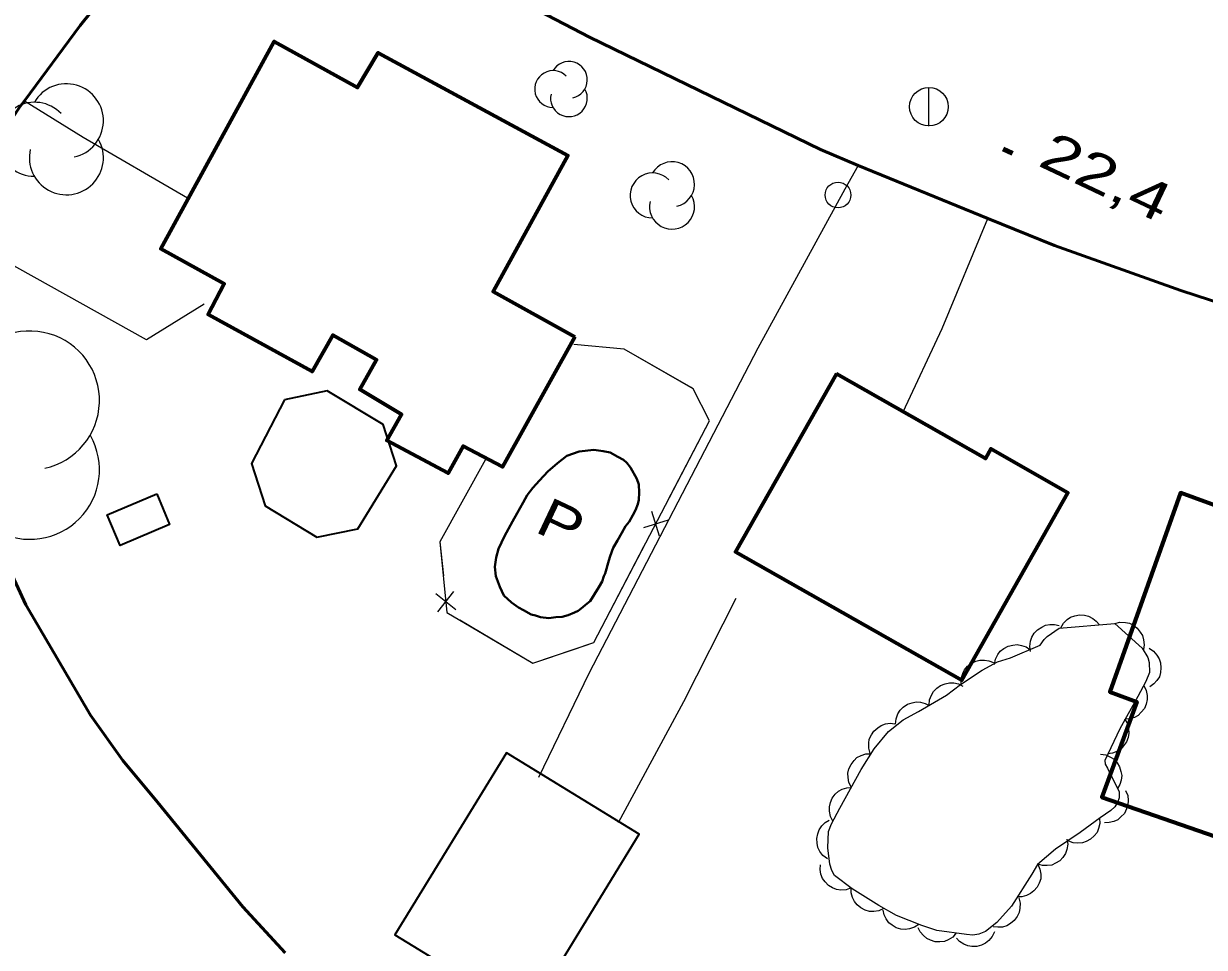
# Model space of a CAD drawing. Extents: x 356765 to 358572, y 5103174 to 5104650.
# Drawn here: x 357286.24 to 357332.12, y 5103742.66 to 5103778.57 of the extents above; entities that cross this region are included whole.
import ezdxf

# ---------------------------------------------------------------- set-up
doc = ezdxf.new("R2010")
doc.units = 0
doc.header["$LTSCALE"] = 0.6
doc.linetypes.add('DOT_DASHED', pattern=[7.7, 5, -1.2, 0.3, -1.2])
for name, color, linetype, lineweight in [('19', 7, 'Continuous', 13), ('21', 7, 'Continuous', 53), ('3', 7, 'Continuous', 140), ('31', 7, 'Continuous', 70), ('36', 7, 'Continuous', 13), ('37', 7, 'Continuous', 13), ('38', 7, 'Continuous', 40), ('44', 7, 'Continuous', 25)]:
    doc.layers.add(name, color=color, linetype=linetype, lineweight=lineweight)

msp = doc.modelspace()

# ---------------------------------------------------------------- linework, layer by layer
at = {"layer": '19'}
for points in [[(357286.27, 5103775.57), (357288.55, 5103774.15), (357292.61, 5103771.8)], [(357318.67, 5103773.06), (357318.15, 5103772.14), (357314.77, 5103765.95), (357308.2, 5103753.31), (357306.24, 5103749.26)], [(357320.42, 5103763.48), (357321.93, 5103766.72), (357323.7, 5103771)], [(357293.25, 5103767.66), (357291.02, 5103766.28), (357283.5, 5103770.46)], [(357309.36, 5103747.52), (357311.89, 5103752.22), (357313.93, 5103756.23)]]:
    msp.add_lwpolyline(points, dxfattribs=at)
at = {"layer": '21'}
for points in [[(357280.14, 5103794.63), (357289.29, 5103788.13), (357299.84, 5103782.26), (357304.62, 5103779.93), (357308.23, 5103778.04), (357317.21, 5103773.67), (357318.67, 5103773.06), (357323.7, 5103771), (357326.29, 5103769.94), (357331.21, 5103768.2), (357336.81, 5103766.37)], [(357283.01, 5103768.41), (357283.3, 5103769.8), (357283.5, 5103770.46), (357283.66, 5103770.96), (357284.91, 5103773.56), (357286.09, 5103775.33), (357286.27, 5103775.57), (357288.44, 5103778.49), (357289.72, 5103780.1), (357290.52, 5103781.01), (357292.93, 5103783.3), (357295.18, 5103784.86)], [(357296.4, 5103742.45), (357294.76, 5103744.23), (357291.44, 5103748.3), (357290.1, 5103749.92), (357288.84, 5103751.69), (357286.33, 5103755.98), (357285.04, 5103758.74)]]:
    msp.add_lwpolyline(points, dxfattribs=at)
at = {"layer": '3'}
msp.add_line((357324.3, 5103773.7), (357324.66, 5103773.53), dxfattribs=at)
at = {"layer": '31'}
for points in [[(357307.66, 5103766.4), (357304.85, 5103761.34), (357303.32, 5103762.15), (357302.73, 5103761.09), (357300.35, 5103762.37), (357300.92, 5103763.38), (357299.31, 5103764.34), (357299.95, 5103765.5), (357298.25, 5103766.46), (357297.45, 5103765.04), (357293.41, 5103767.26), (357294.03, 5103768.46), (357291.57, 5103769.82), (357295.97, 5103777.88), (357299.21, 5103776.09), (357300.01, 5103777.44), (357307.39, 5103773.44), (357304.49, 5103768.16), (357307.66, 5103766.4)], [(357317.82, 5103764.96), (357313.9, 5103758.04), (357322.69, 5103753.05), (357326.82, 5103760.33), (357323.82, 5103762.04), (357323.61, 5103761.67), (357317.82, 5103764.96)], [(357337.58, 5103759.41), (357334.61, 5103760.46), (357334.13, 5103759.26), (357331.19, 5103760.33), (357328.45, 5103752.59), (357329.49, 5103752.21), (357328.14, 5103748.5), (357334.28, 5103746.38), (357334.62, 5103747.4), (357335.54, 5103747.09), (357339.2, 5103757.37), (357337.12, 5103758.16), (357337.58, 5103759.41)]]:
    msp.add_lwpolyline(points, close=True, dxfattribs=at)
at = {"layer": '31', "lineweight": 35}
for points in [[(357296.38, 5103763.95), (357295.09, 5103761.47), (357295.63, 5103759.82), (357297.63, 5103758.61), (357299.22, 5103758.93), (357300.73, 5103761.38), (357300.21, 5103762.98), (357298.03, 5103764.29), (357296.38, 5103763.95)], [(357291.41, 5103760.29), (357291.91, 5103759.1), (357289.99, 5103758.28), (357289.49, 5103759.47), (357291.41, 5103760.29)], [(357305.83, 5103739.98), (357310.16, 5103747.06), (357305, 5103750.22), (357300.67, 5103743.15), (357305.83, 5103739.98)]]:
    msp.add_lwpolyline(points, close=True, dxfattribs=at)
at = {"layer": '36'}
msp.add_line((357321.41, 5103774.58), (357321.41, 5103776.08), dxfattribs=at)
for centre, radius in [((357321.4159, 5103775.3398), 0.75), ((357317.8838, 5103771.9071), 0.5)]:
    msp.add_circle(centre, radius, dxfattribs=at)
at = {"layer": '37'}
for p, q in [((357310.95, 5103758.65), (357310.65, 5103759.6)), ((357311.28, 5103759.27), (357310.32, 5103758.97)), ((357302.26, 5103756.42), (357303.03, 5103755.79)), ((357302.33, 5103755.71), (357302.96, 5103756.49))]:
    msp.add_line(p, q, dxfattribs=at)
for points in [[(357304.19, 5103761.63), (357302.41, 5103758.42), (357302.69, 5103755.68), (357306.03, 5103753.71), (357308.39, 5103754.51), (357312.89, 5103763.13), (357312.26, 5103764.37), (357309.58, 5103765.92), (357307.62, 5103766.09)], [(357312.18, 5103764.42), (357309.58, 5103765.92), (357307.62, 5103766.09)], [(357311.26, 5103760.01), (357312.89, 5103763.13), (357312.26, 5103764.37), (357312.18, 5103764.42)], [(357304.19, 5103761.63), (357302.41, 5103758.42), (357302.55, 5103757.1)], [(357307.64, 5103754.25), (357308.39, 5103754.51), (357310.34, 5103758.24)], [(357303.19, 5103755.39), (357306.03, 5103753.71), (357307.64, 5103754.25)]]:
    msp.add_lwpolyline(points, dxfattribs=at)
at = {"layer": '38'}
msp.add_lwpolyline([(357308.98, 5103757.7), (357309.03, 5103757.87), (357309.15, 5103758.19), (357309.32, 5103758.48), (357309.48, 5103758.78), (357309.63, 5103759.04), (357309.77, 5103759.2), (357309.91, 5103759.46), (357310.02, 5103759.65), (357310.1, 5103759.89), (357310.15, 5103760.06), (357310.16, 5103760.34), (357310.14, 5103760.65), (357310.07, 5103760.88), (357309.82, 5103761.31), (357309.68, 5103761.49), (357309.55, 5103761.61), (357309.33, 5103761.73), (357309.03, 5103761.9), (357308.76, 5103761.95), (357308.4, 5103762), (357307.83, 5103761.94), (357307.35, 5103761.77), (357306.99, 5103761.48), (357306.61, 5103761.16), (357306.28, 5103760.81), (357306.02, 5103760.52), (357305.81, 5103760.24), (357305.65, 5103759.95), (357305.42, 5103759.54), (357305.23, 5103759.21), (357304.92, 5103758.65), (357304.69, 5103758.15), (357304.6, 5103757.81), (357304.55, 5103757.45), (357304.59, 5103757.09), (357304.74, 5103756.67), (357304.9, 5103756.34), (357305.2, 5103756.07), (357305.47, 5103755.87), (357305.66, 5103755.77), (357305.96, 5103755.6), (357306.13, 5103755.56), (357306.33, 5103755.49), (357306.65, 5103755.46), (357306.92, 5103755.5), (357307.17, 5103755.51), (357307.4, 5103755.57), (357307.65, 5103755.68), (357307.79, 5103755.74), (357307.97, 5103755.89), (357308.07, 5103755.98), (357308.25, 5103756.12), (357308.59, 5103756.66), (357308.72, 5103756.88), (357308.78, 5103757.09), (357308.84, 5103757.2), (357308.98, 5103757.7)], close=True, dxfattribs=at)
at = {"layer": '44'}
for points in [[(357326.54, 5103755.08), (357326.64, 5103755.26), (357326.79, 5103755.4), (357326.92, 5103755.5), (357327.09, 5103755.55), (357327.27, 5103755.59), (357327.46, 5103755.57), (357327.62, 5103755.54), (357327.78, 5103755.45), (357327.92, 5103755.34), (357328.04, 5103755.2)], [(357325.37, 5103754.16), (357325.34, 5103754.36), (357325.37, 5103754.56), (357325.42, 5103754.72), (357325.51, 5103754.87), (357325.64, 5103755.01), (357325.8, 5103755.11), (357325.94, 5103755.18), (357326.12, 5103755.21), (357326.3, 5103755.21), (357326.48, 5103755.17)], [(357328.64, 5103755.25), (357328.84, 5103755.3), (357329.05, 5103755.29), (357329.21, 5103755.26), (357329.36, 5103755.18), (357329.51, 5103755.07), (357329.63, 5103754.91), (357329.72, 5103754.78), (357329.76, 5103754.61), (357329.78, 5103754.42), (357329.75, 5103754.24)], [(357323.96, 5103753.66), (357324, 5103753.86), (357324.09, 5103754.04), (357324.19, 5103754.18), (357324.33, 5103754.28), (357324.49, 5103754.37), (357324.68, 5103754.41), (357324.84, 5103754.43), (357325.01, 5103754.4), (357325.19, 5103754.34), (357325.34, 5103754.24)], [(357329.97, 5103754.29), (357330.14, 5103754.18), (357330.27, 5103754.02), (357330.36, 5103753.88), (357330.41, 5103753.72), (357330.43, 5103753.53), (357330.41, 5103753.34), (357330.37, 5103753.18), (357330.27, 5103753.04), (357330.15, 5103752.9), (357330, 5103752.79)], [(357322.67, 5103752.9), (357322.67, 5103753.11), (357322.73, 5103753.3), (357322.8, 5103753.45), (357322.92, 5103753.59), (357323.07, 5103753.7), (357323.24, 5103753.78), (357323.4, 5103753.83), (357323.57, 5103753.83), (357323.75, 5103753.8), (357323.92, 5103753.73)], [(357321.43, 5103752.07), (357321.44, 5103752.28), (357321.52, 5103752.47), (357321.59, 5103752.61), (357321.72, 5103752.74), (357321.87, 5103752.84), (357322.05, 5103752.91), (357322.21, 5103752.95), (357322.38, 5103752.94), (357322.56, 5103752.9), (357322.73, 5103752.82)], [(357329.77, 5103752.84), (357329.86, 5103752.65), (357329.9, 5103752.45), (357329.9, 5103752.29), (357329.86, 5103752.12), (357329.79, 5103751.95), (357329.67, 5103751.8), (357329.55, 5103751.68), (357329.4, 5103751.6), (357329.22, 5103751.54), (357329.04, 5103751.53)], [(357320.12, 5103751.34), (357320.14, 5103751.55), (357320.21, 5103751.74), (357320.3, 5103751.88), (357320.42, 5103752), (357320.58, 5103752.11), (357320.76, 5103752.17), (357320.92, 5103752.2), (357321.09, 5103752.19), (357321.27, 5103752.14), (357321.43, 5103752.06)], [(357319.14, 5103750.2), (357319.08, 5103750.4), (357319.08, 5103750.6), (357319.1, 5103750.76), (357319.18, 5103750.92), (357319.28, 5103751.07), (357319.43, 5103751.2), (357319.56, 5103751.29), (357319.73, 5103751.35), (357319.91, 5103751.37), (357320.09, 5103751.35)], [(357329.02, 5103751.54), (357329.13, 5103751.36), (357329.17, 5103751.16), (357329.19, 5103750.99), (357329.16, 5103750.82), (357329.09, 5103750.65), (357328.98, 5103750.49), (357328.87, 5103750.37), (357328.72, 5103750.28), (357328.55, 5103750.21), (357328.37, 5103750.18)], [(357318.41, 5103748.88), (357318.31, 5103749.07), (357318.28, 5103749.27), (357318.27, 5103749.43), (357318.31, 5103749.6), (357318.39, 5103749.77), (357318.51, 5103749.92), (357318.62, 5103750.04), (357318.78, 5103750.12), (357318.96, 5103750.18), (357319.14, 5103750.19)], [(357328.08, 5103750.17), (357328.29, 5103750.14), (357328.47, 5103750.06), (357328.61, 5103749.97), (357328.73, 5103749.84), (357328.82, 5103749.68), (357328.88, 5103749.5), (357328.91, 5103749.34), (357328.89, 5103749.16), (357328.84, 5103748.99), (357328.75, 5103748.83)], [(357317.68, 5103747.57), (357317.59, 5103747.75), (357317.55, 5103747.96), (357317.55, 5103748.12), (357317.59, 5103748.29), (357317.66, 5103748.46), (357317.78, 5103748.61), (357317.9, 5103748.73), (357318.05, 5103748.81), (357318.23, 5103748.86), (357318.41, 5103748.88)], [(357329.06, 5103748.76), (357329.14, 5103748.57), (357329.16, 5103748.37), (357329.15, 5103748.2), (357329.1, 5103748.04), (357329.01, 5103747.87), (357328.88, 5103747.73), (357328.76, 5103747.62), (357328.6, 5103747.55), (357328.42, 5103747.51), (357328.24, 5103747.5)], [(357328.05, 5103747.68), (357328.06, 5103747.48), (357328.01, 5103747.28), (357327.95, 5103747.13), (357327.84, 5103746.99), (357327.7, 5103746.87), (357327.53, 5103746.78), (357327.38, 5103746.72), (357327.2, 5103746.71), (357327.02, 5103746.73), (357326.85, 5103746.79)], [(357317.47, 5103746.1), (357317.3, 5103746.23), (357317.18, 5103746.39), (357317.1, 5103746.54), (357317.07, 5103746.71), (357317.06, 5103746.89), (357317.1, 5103747.08), (357317.15, 5103747.23), (357317.25, 5103747.38), (357317.39, 5103747.51), (357317.54, 5103747.6)], [(357326.78, 5103746.87), (357326.81, 5103746.67), (357326.77, 5103746.47), (357326.72, 5103746.31), (357326.62, 5103746.16), (357326.5, 5103746.03), (357326.33, 5103745.93), (357326.19, 5103745.86), (357326.01, 5103745.84), (357325.83, 5103745.84), (357325.65, 5103745.89)], [(357318.39, 5103744.97), (357318.2, 5103744.9), (357317.99, 5103744.89), (357317.83, 5103744.91), (357317.67, 5103744.97), (357317.51, 5103745.07), (357317.38, 5103745.21), (357317.28, 5103745.34), (357317.22, 5103745.51), (357317.19, 5103745.69), (357317.2, 5103745.87)], [(357325.65, 5103745.89), (357325.73, 5103745.7), (357325.76, 5103745.5), (357325.76, 5103745.33), (357325.7, 5103745.16), (357325.62, 5103745), (357325.49, 5103744.86), (357325.37, 5103744.75), (357325.21, 5103744.68), (357325.03, 5103744.63), (357324.85, 5103744.62)], [(357319.66, 5103744.17), (357319.47, 5103744.08), (357319.27, 5103744.06), (357319.11, 5103744.06), (357318.94, 5103744.11), (357318.77, 5103744.2), (357318.63, 5103744.32), (357318.52, 5103744.44), (357318.45, 5103744.6), (357318.4, 5103744.78), (357318.39, 5103744.96)], [(357324.91, 5103744.58), (357324.96, 5103744.38), (357324.95, 5103744.18), (357324.92, 5103744.01), (357324.84, 5103743.86), (357324.73, 5103743.71), (357324.58, 5103743.59), (357324.44, 5103743.5), (357324.27, 5103743.45), (357324.09, 5103743.44), (357323.91, 5103743.46)], [(357321.03, 5103743.55), (357320.86, 5103743.44), (357320.66, 5103743.38), (357320.5, 5103743.35), (357320.33, 5103743.37), (357320.15, 5103743.42), (357319.99, 5103743.52), (357319.86, 5103743.62), (357319.75, 5103743.77), (357319.68, 5103743.93), (357319.64, 5103744.11)], [(357322.48, 5103743.22), (357322.34, 5103743.06), (357322.17, 5103742.95), (357322.02, 5103742.89), (357321.84, 5103742.87), (357321.66, 5103742.88), (357321.48, 5103742.94), (357321.33, 5103743), (357321.2, 5103743.12), (357321.08, 5103743.26), (357321, 5103743.42)], [(357323.97, 5103743.27), (357323.88, 5103743.08), (357323.75, 5103742.93), (357323.62, 5103742.82), (357323.46, 5103742.75), (357323.28, 5103742.7), (357323.09, 5103742.7), (357322.93, 5103742.72), (357322.77, 5103742.79), (357322.61, 5103742.89), (357322.49, 5103743.02)]]:
    msp.add_lwpolyline(points, dxfattribs=at)
at = {"layer": '44', "linetype": 'DOT_DASHED'}
msp.add_lwpolyline([(357328.64, 5103755.25), (357329.7, 5103754.29), (357329.92, 5103753.93), (357329.98, 5103753.74), (357329.99, 5103753.34), (357329.85, 5103752.99), (357329.53, 5103752.41), (357328.84, 5103751.16), (357328.25, 5103749.93), (357328.27, 5103749.78), (357328.35, 5103749.63), (357328.81, 5103748.71), (357328.81, 5103748.47), (357328.75, 5103748.29), (357328.64, 5103748.12), (357328.49, 5103747.98), (357328.07, 5103747.7), (357327.29, 5103747.12), (357326.33, 5103746.48), (357325.64, 5103745.88), (357325.41, 5103745.51), (357324.62, 5103744.26), (357324.06, 5103743.63), (357323.61, 5103743.28), (357323.36, 5103743.17), (357323.12, 5103743.13), (357322.88, 5103743.16), (357321.73, 5103743.32), (357321.14, 5103743.51), (357320.16, 5103743.9), (357319.47, 5103744.29), (357318.44, 5103744.93), (357317.75, 5103745.45), (357317.64, 5103745.65), (357317.57, 5103745.9), (357317.49, 5103746.53), (357317.52, 5103747.17), (357317.63, 5103747.46), (357317.96, 5103748.07), (357318.79, 5103749.57), (357319.29, 5103750.38), (357319.84, 5103751.05), (357320.42, 5103751.51), (357321.01, 5103751.83), (357322.1, 5103752.46), (357322.64, 5103752.88), (357323.48, 5103753.44), (357324.08, 5103753.76), (357324.58, 5103753.92), (357325.74, 5103754.41), (357325.89, 5103754.63), (357326.01, 5103754.74), (357326.48, 5103755.07)], close=True, dxfattribs=at)
at = {"layer": '44'}
for centre, radius, start, end in [((357307.4287, 5103776.3838), 0.7151, 282.26917, 149.72626), ((357306.8137, 5103776.0262), 0.7151, 44.11537, 269.80396), ((357287.901, 5103774.7921), 1.4389, 282.26917, 149.72626), ((357307.4287, 5103775.6687), 0.7151, 166.93686, 29.62122), ((357286.6635, 5103774.0727), 1.4389, 44.11537, 269.80396), ((357287.901, 5103773.3532), 1.4389, 166.93686, 29.62122), ((357311.435, 5103772.3269), 0.874, 282.26917, 149.72626), ((357310.6834, 5103771.8898), 0.874, 44.11537, 269.80396), ((357311.435, 5103771.4528), 0.874, 166.93686, 29.62122), ((357286.4873, 5103763.9209), 2.6991, 282.26917, 149.72626), ((357286.4873, 5103761.2217), 2.6991, 166.93686, 29.62122)]:
    msp.add_arc(centre, radius, start, end, dxfattribs=at)

# ---------------------------------------------------------------- texts
at = {"layer": '3', "width": 1.35}
msp.add_text('22,4   ', height=1.5, rotation=334.619, dxfattribs=at).set_placement((357325.6, 5103773.07))
at = {"layer": '38', "width": 1.25}
msp.add_text('P', height=1.5, rotation=334.69, dxfattribs=at).set_placement((357306.05, 5103758.84))

doc.saveas('drawing.dxf')
